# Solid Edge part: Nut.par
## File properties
Author: Sarvanan
Template: sync iso part.par
Last saved by: CADCIM
Revision: 7
Application: Solid Edge
Accuracy: 0.990
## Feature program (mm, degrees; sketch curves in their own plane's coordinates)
sketch for "Hole_1" plane through (21.0838, 43.6973, 12) normal (0, 0, 1) x-axis (1, 0, 0)
  hole centre (-1.3414, 0.2221) bore radius 6
hole "Hole_1" diameter 12 through
pattern "unnamed Pattern 1" of "Hole_1"
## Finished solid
Body 1: solid body, 21 faces, 56 edges, 36 vertices.
  Faces by surface: spun 12, plane 8, cylinder 1
  Edges by curve: circle 18, line 18, intersection 17, spline 3
Bounding box of the edges (mm; curved faces can reach further): 30.022 x 26.000 x 12.000, from (4.7313, 30.9194, 0) to (34.7535, 56.9194, 12).
Cylindrical faces by radius (mm): R6 x1
Planar faces by outward normal: +y 1, +z 1, -y 1, -z 1, oblique 4
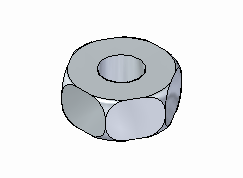
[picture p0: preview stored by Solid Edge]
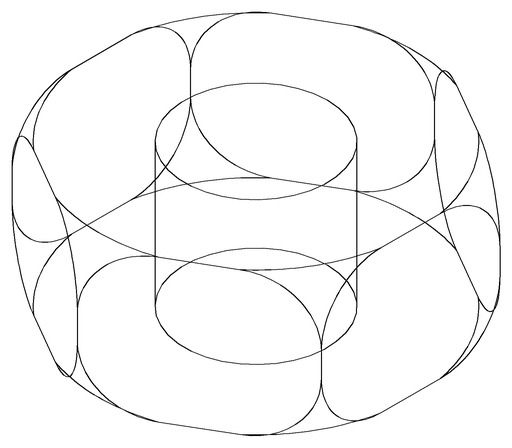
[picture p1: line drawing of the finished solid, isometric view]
